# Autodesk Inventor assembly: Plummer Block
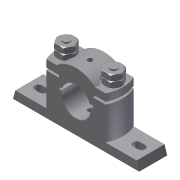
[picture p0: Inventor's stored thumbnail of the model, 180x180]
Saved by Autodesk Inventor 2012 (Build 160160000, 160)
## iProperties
Created: 2011-07
Part Number: Plummer Block
Document SubType Name: Assembly
Designer: CadCim
Author: CadCim
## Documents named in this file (7)
- C:\Users\CadCim\Documents\SAILESH\inventor-2011-fact-prt\c09_inv_2011-prt\c09_inv_2012_prt\Tutorials\c09_tut02_inv\Plummer Block\Plummer Block.iam
- C:\Users\CadCim\Documents\SAILESH\inventor-2011-fact-prt\c09_inv_2011-prt\c09_inv_2012_prt\Tutorials\c09_tut02_inv\Plummer Block\Casting.ipt
- C:\Users\CadCim\Documents\SAILESH\inventor-2011-fact-prt\c09_inv_2011-prt\c09_inv_2012_prt\Tutorials\c09_tut02_inv\Plummer Block\Brasses.ipt
- C:\Users\CadCim\Documents\SAILESH\inventor-2011-fact-prt\c09_inv_2011-prt\c09_inv_2012_prt\Tutorials\c09_tut02_inv\Plummer Block\Cap.ipt
- C:\Users\CadCim\Documents\SAILESH\inventor-2011-fact-prt\c09_inv_2011-prt\c09_inv_2012_prt\Tutorials\c09_tut02_inv\Plummer Block\Bolt.ipt
- C:\Users\CadCim\Documents\SAILESH\inventor-2011-fact-prt\c09_inv_2011-prt\c09_inv_2012_prt\Tutorials\c09_tut02_inv\Plummer Block\Nut.ipt
- C:\Users\CadCim\Documents\SAILESH\inventor-2011-fact-prt\c09_inv_2011-prt\c09_inv_2012_prt\Tutorials\c09_tut02_inv\Plummer Block\Lock Nut.ipt
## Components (9 placed, 6 different names)
1. Casting:1 — Mate:1, Mate:2, Insert:1, Insert:2, Angle:1, Angle:2
2. Brasses:1 — Mate:1, Mate:2, Mate:3, Mate:4
3. Cap:1 — Mate:3, Mate:4, Insert:3, Insert:4
4. Bolt:1 — Insert:1, Angle:1
5. Bolt:2 — Insert:2, Angle:2
6. Nut:1 — Insert:3, Insert:6
7. Nut:2 — Insert:4, Insert:5
8. Lock Nut:1 — Insert:6
9. Lock Nut:2 — Insert:5
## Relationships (12: Insert 6, Mate 4, Angle 2)
- Mate:1: Casting:1 ↔ Brasses:1
- Mate:2: Casting:1 ↔ Brasses:1
- Mate:3: Brasses:1 ↔ Cap:1
- Mate:4: Brasses:1 ↔ Cap:1
- Insert:1: Casting:1 ↔ Bolt:1
- Insert:2: Casting:1 ↔ Bolt:2
- Angle:1: Casting:1 ↔ Bolt:1
- Angle:2: Casting:1 ↔ Bolt:2
- Insert:3: Cap:1 ↔ Nut:1
- Insert:4: Cap:1 ↔ Nut:2
- Insert:5: Nut:2 ↔ Lock Nut:2
- Insert:6: Nut:1 ↔ Lock Nut:1
